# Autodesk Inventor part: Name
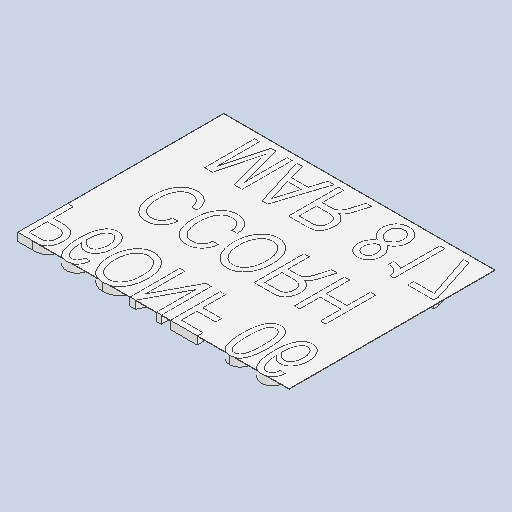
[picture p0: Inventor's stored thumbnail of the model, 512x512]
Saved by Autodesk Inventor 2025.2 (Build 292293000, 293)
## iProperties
Created: 2025-04
Part Number: Name
Material: Generic
Description: PART--DESC
Document SubType Name: Modeling
Designer: BennF
Density: 1 g/cm^3
Appearance: Default
Author: BennF
Revision Number: NONE
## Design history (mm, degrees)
feature "Solid11"
body "Solid1"
